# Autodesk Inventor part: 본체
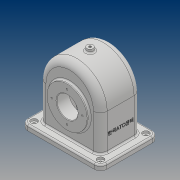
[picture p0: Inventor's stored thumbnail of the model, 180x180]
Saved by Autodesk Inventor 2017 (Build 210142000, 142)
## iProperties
Part Number: 본체
Material: 일반
Document SubType Name: Modeling
Designer: 20
Density: 1 g/cm^3
Appearance: 기본값
Mass: 404.475 g
Surface Area: 1182.21 cm^2
Volume: 404.475 cm^3
Author: 20
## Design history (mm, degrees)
sketch "스케치1"
  geometry: L1 (58, 0)-(58, -78); L2 (58, -78)-(-58, -78); L3 (-58, -78)-(-58, 0); A1 r 58 centre (0, 0) between (58, 0) and (-58, 0); 1 further point
  constraints: 6 end point, 2 point on circle, 2 tangent, 2 vertical, 1 centre point, 1 coincident, 1 horizontal
  dimensions: "d2" = 116 diameter of A1; "d3" = 78 distance from line of L2 point (0, 0)
extrude "돌출1" new body sketch "스케치1" stored distance "d4" = 77; taper "d5" = 0 deg
sketch "스케치2"
  geometry: L1 (52, 0)-(52, -78); L2 (52, -78)-(-52, -78); L3 (-52, -78)-(-52, 0); A1 r 52 centre (0, 0) between (52, 0) and (-52, 0); 1 further point
  constraints: 6 end point, 2 point on circle, 2 tangent, 2 vertical, 1 centre point, 1 coincident, 1 horizontal
  dimensions: "d6" = 104 diameter of A1; "d7" = 78 distance from line of L2 point (0, 0)
extrude "돌출2" cut sketch "스케치2" stored distance "d8" = 67; taper "d9" = 0 deg
sketch "스케치3"
  geometry: L1 (-58, -78)-(58, -78) reference; C1 r 38 at (0, -13); 1 further point
  constraints: 1 centre point, 1 vertical alignment
  dimensions: "d10" = 76 diameter of C1; "d11" = 65 distance from line of L1 C1.centre
extrude "돌출3" join sketch "스케치3" distance "d12" = 5; taper "d13" = 0 deg
sketch "스케치4"
  geometry: L1 (58, 78)-(-58, 78) reference; C1 r 38 at (0, 13); 1 further point
  constraints: 1 centre point, 1 vertical alignment
  dimensions: "d14" = 76 diameter of C1; "d15" = 65 distance from line of L1 C1.centre
extrude "돌출4" join sketch "스케치4" distance "d16" = 10; taper "d17" = 0 deg
sketch "스케치5"
  geometry: L1 (-17, -93.5)-(133, -93.5); L2 (133, -93.5)-(133, 16.5); L3 (133, 16.5)-(-17, 16.5); L4 (-17, 16.5)-(-17, -93.5); L5 (-17, -93.5)-(133, 16.5); L6 (133, -93.5)-(-17, 16.5); L7 (0, 0)-(0, -77) reference; L8 (116, -77)-(0, -77) reference; L9 (0, 0)-(116, 0) reference; L10 (116, 0)-(116, -77) reference; 1 further point
  constraints: 12 end point, 2 midpoint, 2 parallel, 1 horizontal, 1 perpendicular
  dimensions: "d18" = 110 distance of L3.end L1.start; "d19" = 150 distance of L2.end L3.end
extrude "돌출5" join sketch "스케치5" distance "d20" = 10; taper "d21" = 0 deg
node "작업 평면1"
sketch "스케치7"
  geometry: L1 (-52, 78)-(52, 78) reference; C1 r 28 at (0, 13); 1 further point
  constraints: 1 centre point, 1 vertical alignment
  dimensions: "d23" = 56 diameter of C1; "d24" = 65 distance from line of L1 C1.centre
extrude "돌출6" join sketch "스케치7" stored distance "d25" = 14; taper "d26" = 40 deg
sketch "스케치8"
  geometry: C1 r 38 at (0, 0) reference; C2 r 20 at (0, 0); 1 further point
  constraints: 1 centre point, 1 coincident
  dimensions: "d27" = 40 diameter of C2
extrude "돌출7" cut sketch "스케치8" stored distance "d28" = 10; taper "d29" = 0 deg
node "작업 평면2"
sketch "스케치9"
  geometry: C1 r 6 at (75, 55); 1 further point
  constraints: 2 coincident, 1 centre point
  dimensions: "d31" = 12 diameter of C1
extrude "돌출8" join sketch "스케치9" stored distance "d32" = 10; taper "d33" = 5 deg
sketch "스케치10"
  geometry: C1 r 20 at (0, 0) reference; 2 further points
  constraints: 1 vertical alignment
  dimensions: "d34" = 29 distance of point (0, 29) C1.centre
hole "구멍1" sketch "스케치10" at (0, 29) diameter "d35" = 3.242; stored, may be unused: countersink angle "d39" = 90 deg, drill point angle "d41" = 118 deg; dims "d36" = 8, "d37" = 4, "d38" = 2, "d40" = 10
sketch "스케치11"
  geometry: C1 r 28 at (0, 0) reference; 2 further points
  constraints: 1 vertical alignment
  dimensions: "d45" = 29 distance of C1.centre point (0, -29)
hole "구멍2" sketch "스케치11" at (0, -29) diameter "d46" = 3.242; stored, may be unused: countersink angle "d50" = 90 deg, drill point angle "d52" = 118 deg; dims "d47" = 8, "d48" = 4, "d49" = 2, "d51" = 10
fillet "모깎기1" dims "d56" = 12
sketch "스케치12"
  geometry: A1 r 12 centre (-121, -81.5) between (-133, -81.5) and (-121, -93.5) reference; A2 r 12 centre (-121, 4.5) between (-121, 16.5) and (-133, 4.5) reference; A3 r 12 centre (5, 4.5) between (17, 4.5) and (5, 16.5) reference; A4 r 12 centre (5, -81.5) between (5, -93.5) and (17, -81.5) reference; 5 further points
  constraints: 4 coincident
hole "구멍3" sketch "스케치12" at (-121, -81.5), (-121, 4.5), (5, 4.5), (5, -81.5) diameter "d57" = 5; stored, may be unused: countersink angle "d61" = 90 deg, drill point angle "d63" = 118 deg; dims "d58" = 8, "d59" = 12, "d60" = 4, "d62" = 10
fillet "모깎기2" dims "d64" = 13
fillet "모깎기3" dims "d65" = 8
chamfer "모따기1" distance "d66" = 1; stored, may be unused: second distance "d67" = 2, angle "d68" = 45 deg
fillet "모깎기4" dims "d69" = 3
fillet "모깎기5" dims "d70" = 3
hole "구멍4" diameter "d73" = 4.459; stored, may be unused: countersink angle "d77" = 90 deg, drill point angle "d79" = 118 deg; dims "d71" = 10, "d72" = 10, "d74" = 10, "d75" = 12, "d76" = 4, "d78" = 12.8
sketch "스케치13"
  geometry: L1 (0, -13)-(65, -13) reference; L2 (78, 68.5)-(78, -17.5) reference; 2 further points
  constraints: 1 other
  dimensions: "d80" = 38.5 distance from line of L1 point (38, 25.5); "d81" = 40 distance from line of L2 point (38, 25.5)
feature "엠보싱1" sketch "스케치13" dims "d82" = 0.5, "d83" = 0
fillet "모깎기6" dims "d84" = 3
node "솔리드1"
pattern_circular "원형 패턴1" dims angle "d43" = 360 deg
pattern_circular "원형 패턴2" dims angle "d54" = 360 deg
other parameters: "d22" = 14, "d30" = -142
